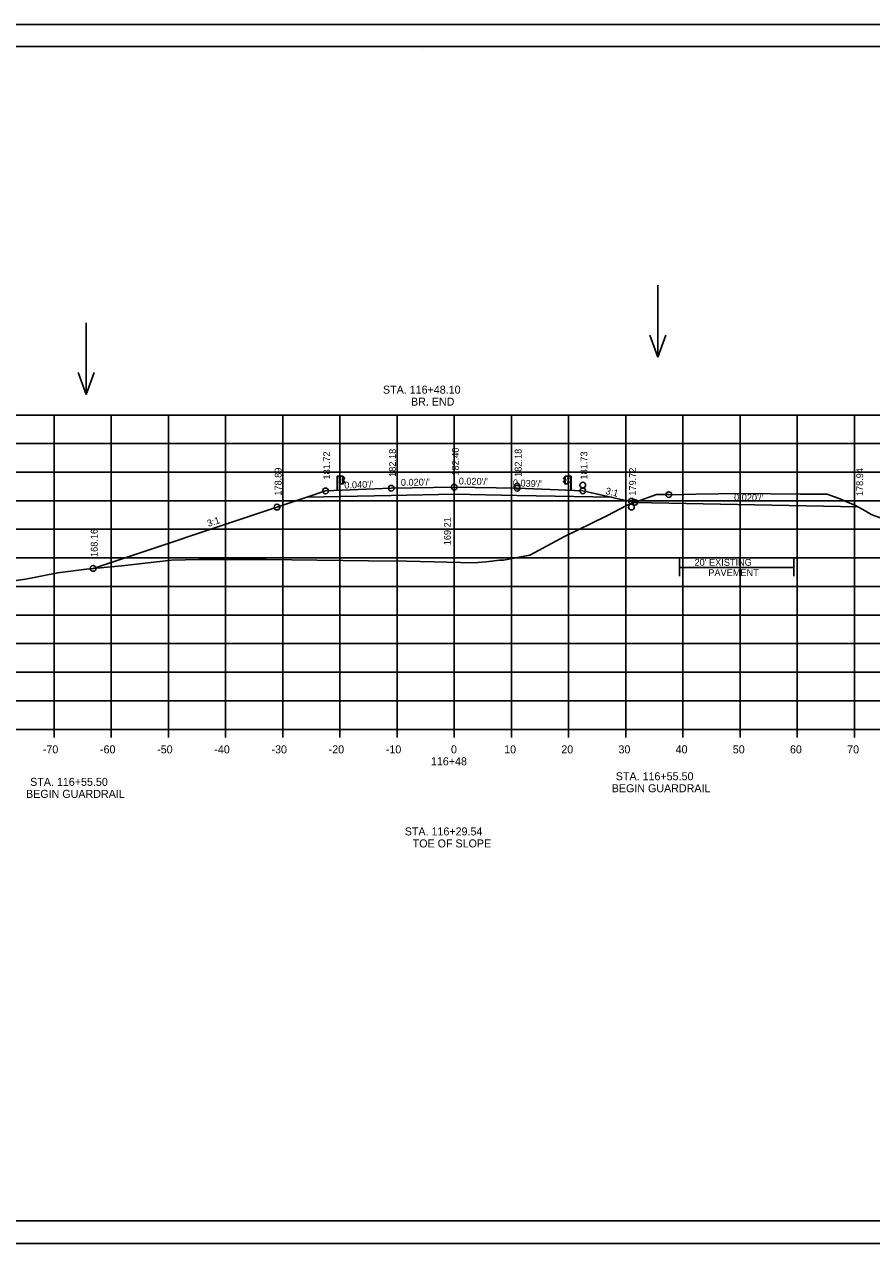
# Model space of a CAD drawing. Extents: x 915787 to 919910, y 133456 to 136717.
# Drawn here: x 916338.8 to 916487, y 135162.7 to 135376.1 of the extents above; entities that cross this region are included whole.
import ezdxf

# ---------------------------------------------------------------- set-up
doc = ezdxf.new("R2010")
doc.units = 0
for name, color, linetype in [('R_Axis', 7, 'Continuous'), ('R_Axis Annot', 7, 'Continuous'), ('R_Border', 7, 'Continuous'), ('R_Border Notes', 7, 'Continuous'), ('R_Drive', 7, 'Continuous'), ('R_Exist Surface', 7, 'Continuous'), ('R_Exist Surface Annot', 7, 'Continuous'), ('R_Fin Surface', 7, 'Continuous'), ('R_Grid', 7, 'Continuous'), ('R_No Plot', 7, 'Continuous'), ('R_Proposed Road', 7, 'Continuous'), ('R_Water', 7, 'Continuous'), ('R_Water Annot', 7, 'Continuous'), ('R_Xsect Elev', 7, 'Continuous'), ('R_Xsect Slope', 7, 'Continuous')]:
    doc.layers.add(name, color=color, linetype=linetype)

msp = doc.modelspace()

# ---------------------------------------------------------------- linework, layer by layer
at = {"layer": 'R_Axis'}
for p, q in [((916273.98, 135252.72), (916553.98, 135252.72)), ((916343.98, 135251.32), (916343.98, 135252.72)), ((916353.98, 135251.32), (916353.98, 135252.72)), ((916363.98, 135251.32), (916363.98, 135252.72)), ((916373.98, 135251.32), (916373.98, 135252.72)), ((916383.98, 135251.32), (916383.98, 135252.72)), ((916393.98, 135251.32), (916393.98, 135252.72)), ((916403.98, 135251.32), (916403.98, 135252.72)), ((916413.98, 135251.32), (916413.98, 135252.72)), ((916423.98, 135251.32), (916423.98, 135252.72)), ((916433.98, 135251.32), (916433.98, 135252.72)), ((916443.98, 135251.32), (916443.98, 135252.72)), ((916453.98, 135251.32), (916453.98, 135252.72)), ((916463.98, 135251.32), (916463.98, 135252.72)), ((916473.98, 135251.32), (916473.98, 135252.72)), ((916483.98, 135251.32), (916483.98, 135252.72))]:
    msp.add_line(p, q, dxfattribs=at)
at = {"layer": 'R_Border'}
for p, q in [((916255.98, 135372.18), (916572.16, 135372.18)), ((916408.5, 135371.92), (916408.5, 135371.92)), ((916408.5, 135371.92), (916408.5, 135371.92)), ((916572.16, 135166.72), (916255.98, 135166.72))]:
    msp.add_line(p, q, dxfattribs=at)
at = {"layer": 'R_Exist Surface'}
msp.add_lwpolyline([(916330.48, 135277.76), (916338.98, 135279.02), (916344.62, 135280.09), (916349.6, 135280.77), (916355.84, 135281.35), (916364.5, 135282.3), (916369.36, 135282.42), (916381.09, 135282.43), (916399, 135282.22), (916405.62, 135282.15), (916410.47, 135282.01), (916417.35, 135281.86), (916419.59, 135282.06), (916421.88, 135282.31), (916422.57, 135282.34), (916427.22, 135283.18), (916433.29, 135286.44), (916437.94, 135288.73), (916440.66, 135290.09), (916444.23, 135291.92), (916445.78, 135292.54), (916449.37, 135293.79), (916451.49, 135293.79), (916452.11, 135293.78), (916456.25, 135293.85), (916464.16, 135294.01), (916474.51, 135293.9), (916475.14, 135293.89), (916475.42, 135293.89), (916479.23, 135293.87), (916481.58, 135292.99), (916482.46, 135292.57), (916484.08, 135291.92), (916485.98, 135290.92), (916486.93, 135290.29), (916490.78, 135288.9)], dxfattribs=at)
at = {"layer": 'R_Exist Surface Annot'}
for p, q in [((916453.37, 135282.54), (916453.37, 135279.54)), ((916473.37, 135282.54), (916473.37, 135279.54)), ((916453.37, 135281.04), (916473.37, 135281.04))]:
    msp.add_line(p, q, dxfattribs=at)
at = {"layer": 'R_Fin Surface'}
for points in [[(916350.8, 135280.88), (916382.97, 135291.61), (916388.22, 135293.35), (916391.47, 135294.44), (916402.97, 135294.9), (916413.97, 135295.12), (916424.97, 135294.9), (916436.47, 135294.44), (916445.52, 135292.44), (916484.57, 135291.66)], [(916388.22, 135293.35), (916402.97, 135293.65), (916413.97, 135293.87), (916424.97, 135293.65), (916441.56, 135293.32)]]:
    msp.add_lwpolyline(points, dxfattribs=at)
at = {"layer": 'R_Grid'}
for p, q in [((916273.98, 135307.72), (916553.98, 135307.72)), ((916343.98, 135252.72), (916343.98, 135307.72)), ((916353.98, 135252.72), (916353.98, 135307.72)), ((916363.98, 135252.72), (916363.98, 135307.72)), ((916373.98, 135252.72), (916373.98, 135307.72)), ((916383.98, 135252.72), (916383.98, 135307.72)), ((916393.98, 135252.72), (916393.98, 135307.72)), ((916403.98, 135252.72), (916403.98, 135307.72)), ((916413.98, 135252.72), (916413.98, 135307.72)), ((916423.98, 135252.72), (916423.98, 135307.72)), ((916433.98, 135252.72), (916433.98, 135307.72)), ((916443.98, 135252.72), (916443.98, 135307.72)), ((916453.98, 135252.72), (916453.98, 135307.72)), ((916463.98, 135252.72), (916463.98, 135307.72)), ((916473.98, 135252.72), (916473.98, 135307.72)), ((916483.98, 135252.72), (916483.98, 135307.72)), ((916273.98, 135302.72), (916553.98, 135302.72)), ((916273.98, 135297.72), (916553.98, 135297.72)), ((916273.98, 135292.72), (916553.98, 135292.72)), ((916273.98, 135287.72), (916553.98, 135287.72)), ((916273.98, 135282.72), (916553.98, 135282.72)), ((916273.98, 135277.72), (916553.98, 135277.72)), ((916273.98, 135272.72), (916553.98, 135272.72)), ((916273.98, 135267.72), (916553.98, 135267.72)), ((916273.98, 135262.72), (916553.98, 135262.72)), ((916273.98, 135257.72), (916553.98, 135257.72)), ((916273.98, 135252.72), (916553.98, 135252.72))]:
    msp.add_line(p, q, dxfattribs=at)
at = {"layer": 'R_No Plot'}
for p, q in [((916243.57, 135376.07), (916576.91, 135376.07)), ((916243.57, 135162.74), (916576.91, 135162.74))]:
    msp.add_line(p, q, dxfattribs=at)
for points in [[(916243.57, 135376.07), (916576.91, 135376.07), (916576.91, 135162.74), (916243.57, 135162.74)], [(916489.9, 135372.18), (916489.9, 135362.3), (916525.63, 135362.3), (916525.63, 135359.38), (916548.83, 135359.38), (916548.83, 135336.16), (916572.16, 135336.16), (916572.16, 135166.72), (916255.98, 135166.72), (916255.98, 135372.18)]]:
    msp.add_lwpolyline(points, close=True, dxfattribs=at)
for centre in [(916391.47, 135294.44), (916391.47, 135294.44), (916402.97, 135294.9), (916402.97, 135294.9), (916413.97, 135295.12), (916413.97, 135295.12), (916424.97, 135295.29), (916424.97, 135294.9), (916436.47, 135295.46), (916436.47, 135294.44), (916444.97, 135292.63), (916445.54, 135292.44), (916451.5, 135293.79), (916451.5, 135293.79), (916382.97, 135291.61), (916382.97, 135291.61), (916444.97, 135291.61), (916350.8, 135280.88), (916350.8, 135280.88)]:
    msp.add_circle(centre, 0.5, dxfattribs=at)
at = {"layer": 'R_Proposed Road'}
for p, q in [((916393.47, 135297.03), (916393.47, 135294.52)), ((916393.5, 135297.03), (916393.5, 135294.52)), ((916393.87, 135296.62), (916393.87, 135296.71)), ((916393.93, 135296.73), (916393.88, 135296.73)), ((916393.93, 135296.7), (916393.88, 135296.7)), ((916393.93, 135296.64), (916393.88, 135296.64)), ((916393.93, 135296.6), (916393.88, 135296.6)), ((916393.93, 135296.64), (916393.89, 135296.64)), ((916394, 135297.03), (916393.93, 135297.03)), ((916393.93, 135296.6), (916393.93, 135296.73)), ((916393.97, 135294.51), (916393.97, 135297.03)), ((916394, 135297.03), (916393.99, 135297.03)), ((916394.05, 135296.66), (916394, 135296.66)), ((916394.01, 135296.72), (916394.06, 135296.72)), ((916394.01, 135296.6), (916394.06, 135296.6)), ((916394.06, 135296.72), (916394.06, 135296.6)), ((916394.5, 135295.66), (916394.5, 135297.02)), ((916394.64, 135296.82), (916394.53, 135296.88)), ((916394.63, 135296.8), (916394.54, 135296.85)), ((916394.58, 135296.48), (916394.76, 135296.59)), ((916394.76, 135296.7), (916394.63, 135296.8)), ((916394.77, 135296.71), (916394.64, 135296.82)), ((916433.14, 135296.72), (916433.27, 135296.82)), ((916433.31, 135296.47), (916433.14, 135296.58)), ((916433.15, 135296.7), (916433.28, 135296.81)), ((916433.32, 135296.49), (916433.15, 135296.6)), ((916433.27, 135296.82), (916433.38, 135296.88)), ((916433.28, 135296.81), (916433.37, 135296.86)), ((916433.41, 135295.67), (916433.41, 135297.03)), ((916433.9, 135296.73), (916433.85, 135296.73)), ((916433.85, 135296.73), (916433.85, 135296.61)), ((916433.85, 135296.67), (916433.91, 135296.67)), ((916433.9, 135296.61), (916433.85, 135296.61)), ((916433.91, 135297.04), (916433.91, 135297.04)), ((916433.91, 135297.04), (916433.98, 135297.04)), ((916433.94, 135294.52), (916433.94, 135297.04)), ((916433.98, 135296.61), (916433.98, 135296.74)), ((916433.98, 135296.74), (916434.03, 135296.74)), ((916433.98, 135296.71), (916434.03, 135296.71)), ((916433.98, 135296.64), (916434.02, 135296.64)), ((916433.98, 135296.64), (916434.03, 135296.64)), ((916433.98, 135296.61), (916434.03, 135296.61)), ((916434.03, 135296.63), (916434.03, 135296.72)), ((916434.4, 135297.04), (916434.4, 135294.52)), ((916434.43, 135297.04), (916434.43, 135294.52)), ((916393.86, 135295.93), (916393.86, 135296.03)), ((916393.92, 135296.04), (916393.87, 135296.04)), ((916393.92, 135296.01), (916393.87, 135296.01)), ((916393.92, 135295.95), (916393.87, 135295.95)), ((916393.92, 135295.92), (916393.87, 135295.92)), ((916393.92, 135295.95), (916393.88, 135295.95)), ((916393.92, 135295.92), (916393.92, 135296.04)), ((916394, 135295.66), (916393.96, 135295.66)), ((916394.05, 135295.98), (916394, 135295.98)), ((916394.06, 135296.04), (916394.01, 135296.04)), ((916394.06, 135295.92), (916394.01, 135295.92)), ((916394.06, 135295.92), (916394.06, 135296.04)), ((916394.43, 135296.3), (916394.43, 135296.39)), ((916394.49, 135296.41), (916394.44, 135296.41)), ((916394.49, 135296.38), (916394.44, 135296.38)), ((916394.49, 135296.31), (916394.44, 135296.31)), ((916394.49, 135296.31), (916394.44, 135296.31)), ((916394.49, 135296.28), (916394.44, 135296.28)), ((916394.49, 135296.28), (916394.49, 135296.41)), ((916394.53, 135295.83), (916394.63, 135295.88)), ((916394.53, 135295.81), (916394.65, 135295.87)), ((916394.54, 135296.28), (916394.54, 135296.42)), ((916394.56, 135296.28), (916394.56, 135296.42)), ((916394.73, 135296.11), (916394.58, 135296.21)), ((916394.75, 135296.13), (916394.59, 135296.23)), ((916394.6, 135296.46), (916394.77, 135296.57)), ((916394.63, 135295.88), (916394.76, 135295.99)), ((916394.65, 135295.87), (916394.77, 135295.97)), ((916433.26, 135295.87), (916433.13, 135295.98)), ((916433.27, 135295.89), (916433.15, 135296)), ((916433.16, 135296.14), (916433.32, 135296.24)), ((916433.17, 135296.12), (916433.33, 135296.22)), ((916433.37, 135295.81), (916433.26, 135295.87)), ((916433.38, 135295.83), (916433.27, 135295.89)), ((916433.35, 135296.29), (916433.34, 135296.42)), ((916433.37, 135296.29), (916433.37, 135296.42)), ((916433.42, 135296.29), (916433.42, 135296.42)), ((916433.42, 135296.42), (916433.47, 135296.42)), ((916433.42, 135296.38), (916433.47, 135296.38)), ((916433.42, 135296.32), (916433.47, 135296.32)), ((916433.42, 135296.32), (916433.47, 135296.32)), ((916433.42, 135296.29), (916433.47, 135296.29)), ((916433.48, 135296.31), (916433.48, 135296.4)), ((916433.85, 135295.92), (916433.85, 135296.05)), ((916433.85, 135296.05), (916433.9, 135296.05)), ((916433.85, 135295.98), (916433.91, 135295.98)), ((916433.85, 135295.92), (916433.9, 135295.92)), ((916433.91, 135295.67), (916433.94, 135295.67)), ((916433.99, 135295.92), (916433.99, 135296.05)), ((916433.99, 135296.05), (916434.04, 135296.05)), ((916433.99, 135296.02), (916434.04, 135296.02)), ((916433.99, 135295.95), (916434.03, 135295.95)), ((916433.99, 135295.95), (916434.04, 135295.95)), ((916433.99, 135295.92), (916434.04, 135295.92)), ((916434.04, 135295.94), (916434.04, 135296.03))]:
    msp.add_line(p, q, dxfattribs=at)
for points in [[(916393.47, 135297.03), (916393.93, 135297.03), (916393.93, 135294.51)], [(916434.43, 135297.04), (916433.98, 135297.04), (916433.98, 135294.52)]]:
    msp.add_lwpolyline(points, dxfattribs=at)
for points in [[(916393.87, 135296.7), (916393.87, 135296.64), (916393.85, 135296.64), (916393.85, 135296.7)], [(916393.93, 135296.75), (916393.93, 135296.58), (916393.94, 135296.58), (916393.94, 135296.75)], [(916394.52, 135297.03), (916394.52, 135295.66), (916394, 135295.66), (916394, 135297.03)], [(916394.05, 135296.72), (916394.05, 135296.6), (916394, 135296.6), (916394, 135296.72)], [(916433.38, 135297.04), (916433.38, 135295.67), (916433.91, 135295.67), (916433.91, 135297.04)], [(916433.85, 135296.73), (916433.85, 135296.61), (916433.91, 135296.61), (916433.91, 135296.73)], [(916433.98, 135296.76), (916433.98, 135296.59), (916433.97, 135296.59), (916433.97, 135296.76)], [(916434.04, 135296.71), (916434.04, 135296.64), (916434.06, 135296.64), (916434.06, 135296.71)], [(916393.86, 135296.01), (916393.86, 135295.95), (916393.84, 135295.95), (916393.84, 135296.01)], [(916393.92, 135296.06), (916393.92, 135295.89), (916393.93, 135295.89), (916393.93, 135296.06)], [(916394.05, 135296.04), (916394.05, 135295.92), (916394, 135295.92), (916394, 135296.04)], [(916394.43, 135296.38), (916394.43, 135296.31), (916394.4, 135296.31), (916394.4, 135296.38)], [(916394.48, 135296.43), (916394.48, 135296.26), (916394.49, 135296.26), (916394.49, 135296.43)], [(916433.42, 135296.44), (916433.42, 135296.27), (916433.41, 135296.27), (916433.41, 135296.44)], [(916433.48, 135296.38), (916433.48, 135296.32), (916433.5, 135296.32), (916433.5, 135296.38)], [(916433.85, 135296.05), (916433.85, 135295.92), (916433.91, 135295.92), (916433.91, 135296.05)], [(916433.99, 135296.07), (916433.99, 135295.9), (916433.98, 135295.9), (916433.98, 135296.07)], [(916434.05, 135296.02), (916434.05, 135295.95), (916434.07, 135295.95), (916434.07, 135296.02)]]:
    msp.add_lwpolyline(points, close=True, dxfattribs=at)
for centre, radius, start, end in [((916393.9, 135296.71), 0.022, 134.5745, 222.2244), ((916393.97, 135296.67), 0.0922, 159.7423, 200.2577), ((916393.9, 135296.62), 0.025, 140.9334, 216.6234), ((916394.73, 135296.64), 0.062, 299.2499, 57.9783), ((916394.73, 135296.64), 0.0856, 299.2499, 57.9783), ((916433.18, 135296.65), 0.0856, 122.0217, 240.7501), ((916433.18, 135296.65), 0.062, 122.0217, 240.7501), ((916434.01, 135296.72), 0.022, 317.7756, 45.4255), ((916433.94, 135296.67), 0.0922, 339.7423, 20.2577), ((916434.01, 135296.63), 0.025, 323.3766, 39.0666), ((916393.89, 135296.02), 0.022, 134.5745, 222.2244), ((916393.96, 135295.98), 0.0922, 159.7423, 200.2577), ((916393.89, 135295.93), 0.025, 140.9334, 216.6234), ((916394.45, 135296.39), 0.022, 134.5745, 222.2244), ((916394.52, 135296.35), 0.0922, 159.7423, 200.2577), ((916394.46, 135296.3), 0.025, 140.9334, 216.6234), ((916394.63, 135296.41), 0.0865, 118.106, 175.0444), ((916394.61, 135296.27), 0.0703, 171.7804, 246.8536), ((916394.63, 135296.41), 0.0622, 118.106, 175.0444), ((916394.56, 135296.34), 0.0453, 282.9554, 86.0697), ((916394.61, 135296.27), 0.0462, 171.7804, 246.8536), ((916394.69, 135296.04), 0.0854, 325.2184, 59.12), ((916394.69, 135296.04), 0.109, 325.2184, 59.12), ((916433.22, 135296.05), 0.109, 120.88, 214.7816), ((916433.22, 135296.05), 0.0854, 120.88, 214.7816), ((916433.28, 135296.41), 0.0622, 4.9556, 61.894), ((916433.35, 135296.35), 0.0453, 93.9303, 257.0446), ((916433.28, 135296.41), 0.0865, 4.9556, 61.894), ((916433.3, 135296.28), 0.0462, 293.1464, 8.2196), ((916433.3, 135296.28), 0.0703, 293.1464, 8.2196), ((916433.46, 135296.4), 0.022, 317.7756, 45.4255), ((916433.39, 135296.35), 0.0922, 339.7423, 20.2577), ((916433.45, 135296.3), 0.025, 323.3766, 39.0666), ((916434.02, 135296.03), 0.022, 317.7756, 45.4255), ((916433.95, 135295.98), 0.0922, 339.7423, 20.2577), ((916434.02, 135295.94), 0.025, 323.3766, 39.0666)]:
    msp.add_arc(centre, radius, start, end, dxfattribs=at)
at = {"layer": 'R_Water'}
msp.add_line((916445.54, 135292.44), (916484.57, 135291.66), dxfattribs=at)
at = {"layer": 'R_Water Annot'}
for p, q in [((916449.61, 135330.43), (916449.61, 135317.86)), ((916349.58, 135323.88), (916349.58, 135311.31)), ((916449.61, 135317.86), (916448.21, 135321.71)), ((916449.61, 135317.86), (916451.01, 135321.71)), ((916349.58, 135311.31), (916348.18, 135315.16)), ((916349.58, 135311.31), (916350.98, 135315.16))]:
    msp.add_line(p, q, dxfattribs=at)

# ---------------------------------------------------------------- texts
at = {"layer": 'R_Axis Annot'}
for s, p in [('-70', (916342.01, 135248.52)), ('-60', (916352.01, 135248.52)), ('-50', (916362.01, 135248.52)), ('-40', (916372.01, 135248.52)), ('-30', (916382.01, 135248.52)), ('-20', (916392.01, 135248.52)), ('-10', (916402.01, 135248.52)), ('0', (916413.41, 135248.52)), ('10', (916422.71, 135248.52)), ('20', (916432.71, 135248.52)), ('30', (916442.71, 135248.52)), ('40', (916452.71, 135248.52)), ('50', (916462.71, 135248.52)), ('60', (916472.71, 135248.52)), ('70', (916482.71, 135248.52)), ('116+48', (916409.9, 135246.42))]:
    msp.add_text(s, height=1.4, dxfattribs=at).set_placement(p)
at = {"layer": 'R_Border Notes'}
for s, p in [('STA. 116+48.10', (916401.51, 135311.46)), ('BR. END', (916406.41, 135309.36)), ('STA. 116+29.54', (916405.32, 135234.16)), ('TOE OF SLOPE', (916406.71, 135232.06))]:
    msp.add_text(s, height=1.4, dxfattribs=at).set_placement(p)
at = {"layer": 'R_Drive'}
for s, p in [('STA. 116+55.50', (916339.79, 135242.83)), ('STA. 116+55.50', (916442.24, 135243.81)), ('BEGIN GUARDRAIL', (916339.07, 135240.73)), ('BEGIN GUARDRAIL', (916441.53, 135241.71))]:
    msp.add_text(s, height=1.4, dxfattribs=at).set_placement(p)
at = {"layer": 'R_Exist Surface Annot'}
for s, p in [("20' EXISTING", (916456.01, 135281.34)), ('PAVEMENT', (916458.42, 135279.54))]:
    msp.add_text(s, height=1.2, dxfattribs=at).set_placement(p)
at = {"layer": 'R_Xsect Elev'}
for s, p in [('181.72', (916392.27, 135296.44)), ('182.18', (916403.77, 135296.9)), ('182.40', (916414.77, 135297.12)), ('182.18', (916425.77, 135296.9)), ('181.73', (916437.27, 135296.44)), ('178.89', (916383.77, 135293.61)), ('179.72', (916445.77, 135293.61)), ('178.94', (916485.51, 135293.53)), ('169.21', (916413.38, 135284.93)), ('168.16', (916351.6, 135282.88))]:
    msp.add_text(s, height=1.2, rotation=90, dxfattribs=at).set_placement(p)
at = {"layer": 'R_Xsect Slope'}
for s, rotation, p in [("0.020'/'", 1.1458, (916404.65, 135295.31)), ("0.020'/'", 358.8542, (916414.76, 135295.58)), ("0.040'/'", 2.2906, (916394.77, 135294.84)), ("0.039'/'", 357.739, (916424.21, 135295.27)), ('3:1', 346.4325, (916440.36, 135293.91)), ("0.020'/'", 358.8542, (916462.92, 135292.74)), ('3:1', 18.4349, (916370.98, 135288.13))]:
    msp.add_text(s, height=1.2, rotation=rotation, dxfattribs=at).set_placement(p)

doc.saveas('drawing.dxf')
